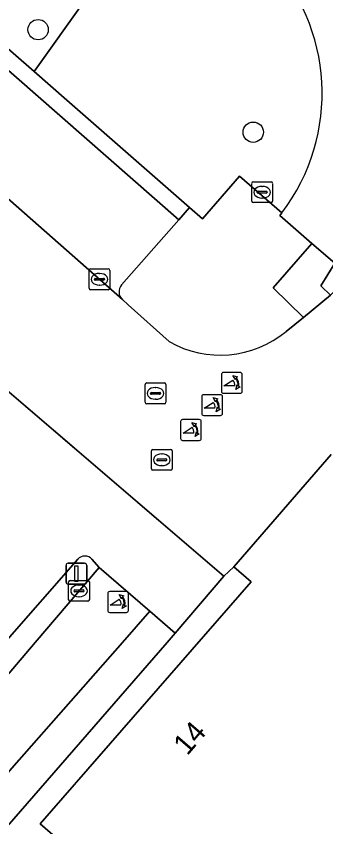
# Model space of a CAD drawing. Extents: x 158472 to 159562, y 388525 to 389606.
# Drawn here: x 158841.56 to 158856.42, y 388741.16 to 388780.05 of the extents above; entities that cross this region are included whole.
import ezdxf

# ---------------------------------------------------------------- set-up
doc = ezdxf.new("R2010")
doc.units = 0
for name, color, linetype in [('IMGEO_Boom', 7, 'Continuous'), ('IMGEO_Brandkraan', 7, 'Continuous'), ('IMGEO_Fietspad_gesloten', 7, 'Continuous'), ('IMGEO_Groenvoorziening', 7, 'Continuous'), ('IMGEO_Haag', 7, 'Continuous'), ('IMGEO_Kolk', 7, 'Continuous'), ('IMGEO_Lichtmast', 7, 'Continuous'), ('IMGEO_Pand', 7, 'Continuous'), ('IMGEO_Pand_nummerreeks', 7, 'Continuous'), ('IMGEO_Parkeervlak_open', 7, 'Continuous'), ('IMGEO_Poller', 7, 'Continuous'), ('IMGEO_Rijbaan_lokaal_open', 7, 'Continuous'), ('IMGEO_Rioolput', 7, 'Continuous'), ('IMGEO_Voetpad_open', 7, 'Continuous')]:
    doc.layers.add(name, color=color, linetype=linetype)

msp = doc.modelspace()

# ---------------------------------------------------------------- linework, layer by layer
at = {"layer": 'IMGEO_Boom'}
for centre in [(158842.61, 388779.402), (158852.939, 388774.483)]:
    msp.add_circle(centre, 0.489, dxfattribs=at)
at = {"layer": 'IMGEO_Brandkraan'}
for p, q in [((158852.867, 388771.178), (158852.867, 388772.03)), ((158852.942, 388772.104), (158853.794, 388772.104)), ((158853.868, 388772.03), (158853.868, 388771.178)), ((158853.126, 388771.598), (158853.126, 388771.61)), ((158853.169, 388771.647), (158853.567, 388771.647)), ((158853.355, 388771.884), (158853.38, 388771.884)), ((158853.61, 388771.61), (158853.61, 388771.598)), ((158853.564, 388771.561), (158853.166, 388771.561)), ((158853.378, 388771.324), (158853.353, 388771.324)), ((158853.794, 388771.104), (158852.942, 388771.104))]:
    msp.add_line(p, q, dxfattribs=at)
for points in [[(158852.867, 388771.178), (158852.867, 388772.03)], [(158852.942, 388772.104), (158853.794, 388772.104)], [(158853.868, 388772.03), (158853.868, 388771.178)], [(158853.794, 388771.104), (158852.942, 388771.104)]]:
    msp.add_lwpolyline(points, dxfattribs=at)
for centre, radius, start, end in [((158852.944, 388772.028), 0.0765, 91.552, 178.448), ((158852.944, 388772.028), 0.0765, 91.552, 178.448), ((158853.792, 388772.028), 0.0765, 1.552, 88.448), ((158853.792, 388772.028), 0.0765, 1.552, 88.448), ((158853.166, 388771.607), 0.0403, 85.8775, 175.7526), ((158853.163, 388771.597), 0.0366, 178.938, 274.7102), ((158853.567, 388771.604), 0.043, 264.8664, 352.4533), ((158853.571, 388771.609), 0.0386, 1.7309, 96.639), ((158852.944, 388771.18), 0.0765, 181.552, 268.448), ((158852.944, 388771.18), 0.0765, 181.552, 268.448), ((158853.792, 388771.18), 0.0765, 271.552, 358.448), ((158853.792, 388771.18), 0.0765, 271.552, 358.448)]:
    msp.add_arc(centre, radius, start, end, dxfattribs=at)
for centre, major_axis, ratio, start_param, end_param in [((158853.354, 388771.604), (-0.387, 0.002), 0.722429, 4.712389, 7.853982), ((158853.379, 388771.604), (-0.39, 0.002), 0.717154, 1.570796, 4.712389)]:
    msp.add_ellipse(centre, major_axis=major_axis, ratio=ratio, start_param=start_param, end_param=end_param, dxfattribs=at)
at = {"layer": 'IMGEO_Fietspad_gesloten'}
msp.add_lwpolyline([(158810.886, 388711.732), (158812.719, 388711.297), (158814.869, 388710.787), (158814.869, 388710.788), (158815.7, 388711.945), (158815.926, 388712.258), (158824.309, 388722.191), (158828.494, 388729.091), (158841.352, 388743.973), (158846.666, 388750), (158847.968, 388751.505), (158845.533, 388753.604), (158842.47, 388750), (158830.472, 388735.881), (158829.07, 388734.265), (158828.323, 388733.403), (158828.113, 388733.162), (158826.147, 388730.896), (158821.352, 388724.146), (158817.275, 388719.548), (158816.62, 388718.761), (158811.748, 388712.776), (158810.886, 388711.732), (158810.886, 388711.732)], dxfattribs=at)
at = {"layer": 'IMGEO_Groenvoorziening'}
for points in [[(158868.786, 388781.968), (158856.961, 388768.353), (158856.858, 388768.202), (158856.185, 388767.106), (158856.64, 388766.667), (158865.091, 388774.661), (158872.19, 388781.908), (158872.356, 388782.085), (158872.522, 388782.263), (158883.327, 388794.483)], [(158853.619, 388782.898), (158855.447, 388784.891), (158851.58, 388788.308), (158844.852, 388780.806), (158842.418, 388777.388), (158843.993, 388776.012), (158849.885, 388770.864), (158850.507, 388770.321), (158852.278, 388772.366), (158854.314, 388770.621)], [(158855.756, 388769.138), (158854.216, 388770.482), (158854.314, 388770.621), (158852.278, 388772.366), (158850.507, 388770.321), (158849.885, 388770.864), (158849.366, 388770.272), (158846.619, 388767.157)], [(158854.525, 388764.929), (158855.357, 388765.589), (158853.888, 388767.011), (158855.756, 388769.138)], [(158846.659, 388766.452), (158846.938, 388766.2), (158848.898, 388764.436)], [(158844.515, 388754.003), (158841.019, 388750), (158828.051, 388735.145), (158829.07, 388734.265), (158830.472, 388735.881), (158842.47, 388750)], [(158842.47, 388750), (158845.533, 388753.604), (158845.196, 388754.006)]]:
    msp.add_lwpolyline(points, dxfattribs=at)
msp.add_lwpolyline([(158834.211, 388789.462), (158831.754, 388786.709), (158832.697, 388785.881), (158842.418, 388777.388), (158844.852, 388780.806)], close=True, dxfattribs=at)
for centre, radius, start, end in [((158846.775, 388776.352), 9.47, 322.758, 43.7221), ((158846.995, 388766.825), 0.502, 138.5236, 227.971), ((158851.354, 388768.766), 4.978, 240.4377, 309.5764), ((158844.857, 388753.676), 0.473, 44.2622, 136.2426)]:
    msp.add_arc(centre, radius, start, end, dxfattribs=at)
at = {"layer": 'IMGEO_Haag'}
for points in [[(158868.786, 388781.968), (158856.961, 388768.353), (158856.858, 388768.202), (158856.185, 388767.106), (158856.64, 388766.667), (158865.091, 388774.661), (158872.19, 388781.908), (158872.356, 388782.085), (158872.522, 388782.263), (158883.327, 388794.483)], [(158844.515, 388754.003), (158841.019, 388750), (158828.051, 388735.145), (158829.07, 388734.265), (158830.472, 388735.881), (158842.47, 388750)], [(158842.47, 388750), (158845.533, 388753.604), (158845.196, 388754.006)]]:
    msp.add_lwpolyline(points, dxfattribs=at)
msp.add_arc((158844.857, 388753.676), 0.473, 44.2622, 136.2426, dxfattribs=at)
at = {"layer": 'IMGEO_Kolk'}
for p, q in [((158845.053, 388767.001), (158845.053, 388767.853)), ((158845.128, 388767.927), (158845.98, 388767.927)), ((158845.541, 388767.707), (158845.566, 388767.707)), ((158846.054, 388767.853), (158846.054, 388767.001)), ((158845.312, 388767.421), (158845.312, 388767.433)), ((158845.75, 388767.384), (158845.352, 388767.384)), ((158845.355, 388767.47), (158845.753, 388767.47)), ((158845.796, 388767.433), (158845.796, 388767.421)), ((158845.98, 388766.927), (158845.128, 388766.927)), ((158845.564, 388767.147), (158845.539, 388767.147)), ((158848.046, 388758.341), (158848.046, 388759.193)), ((158848.121, 388759.267), (158848.973, 388759.267)), ((158849.047, 388759.193), (158849.047, 388758.341)), ((158848.305, 388758.761), (158848.305, 388758.773)), ((158848.348, 388758.81), (158848.746, 388758.81)), ((158848.534, 388759.047), (158848.559, 388759.047)), ((158848.789, 388758.773), (158848.789, 388758.761)), ((158848.743, 388758.724), (158848.345, 388758.724)), ((158848.557, 388758.487), (158848.532, 388758.487)), ((158848.973, 388758.267), (158848.121, 388758.267)), ((158844.073, 388752.055), (158844.073, 388752.907)), ((158844.148, 388752.981), (158845, 388752.981)), ((158845.074, 388752.907), (158845.074, 388752.055)), ((158844.375, 388752.524), (158844.773, 388752.524)), ((158844.561, 388752.761), (158844.586, 388752.761)), ((158844.332, 388752.475), (158844.332, 388752.487)), ((158844.77, 388752.438), (158844.372, 388752.438)), ((158844.584, 388752.201), (158844.559, 388752.201)), ((158844.816, 388752.487), (158844.816, 388752.475)), ((158845, 388751.981), (158844.148, 388751.981))]:
    msp.add_line(p, q, dxfattribs=at)
for points in [[(158845.053, 388767.001), (158845.053, 388767.853)], [(158845.128, 388767.927), (158845.98, 388767.927)], [(158846.054, 388767.853), (158846.054, 388767.001)], [(158845.98, 388766.927), (158845.128, 388766.927)], [(158848.046, 388758.341), (158848.046, 388759.193)], [(158848.121, 388759.267), (158848.973, 388759.267)], [(158849.047, 388759.193), (158849.047, 388758.341)], [(158848.973, 388758.267), (158848.121, 388758.267)], [(158844.073, 388752.055), (158844.073, 388752.907)], [(158844.148, 388752.981), (158845, 388752.981)], [(158845.074, 388752.907), (158845.074, 388752.055)], [(158845, 388751.981), (158844.148, 388751.981)]]:
    msp.add_lwpolyline(points, dxfattribs=at)
for centre, radius, start, end in [((158845.13, 388767.851), 0.0765, 91.552, 178.448), ((158845.13, 388767.851), 0.0765, 91.552, 178.448), ((158845.978, 388767.851), 0.0765, 1.552, 88.448), ((158845.978, 388767.851), 0.0765, 1.552, 88.448), ((158845.352, 388767.43), 0.0403, 85.8775, 175.7526), ((158845.349, 388767.42), 0.0366, 178.938, 274.7102), ((158845.753, 388767.427), 0.043, 264.8664, 352.4533), ((158845.757, 388767.432), 0.0386, 1.7309, 96.639), ((158845.13, 388767.003), 0.0765, 181.552, 268.448), ((158845.13, 388767.003), 0.0765, 181.552, 268.448), ((158845.978, 388767.003), 0.0765, 271.552, 358.448), ((158845.978, 388767.003), 0.0765, 271.552, 358.448), ((158848.123, 388759.191), 0.0765, 91.552, 178.448), ((158848.123, 388759.191), 0.0765, 91.552, 178.448), ((158848.971, 388759.191), 0.0765, 1.552, 88.448), ((158848.971, 388759.191), 0.0765, 1.552, 88.448), ((158848.345, 388758.77), 0.0403, 85.8775, 175.7526), ((158848.342, 388758.76), 0.0366, 178.938, 274.7102), ((158848.746, 388758.767), 0.043, 264.8664, 352.4533), ((158848.75, 388758.772), 0.0386, 1.7309, 96.639), ((158848.123, 388758.343), 0.0765, 181.552, 268.448), ((158848.123, 388758.343), 0.0765, 181.552, 268.448), ((158848.971, 388758.343), 0.0765, 271.552, 358.448), ((158848.971, 388758.343), 0.0765, 271.552, 358.448), ((158844.15, 388752.905), 0.0765, 91.552, 178.448), ((158844.15, 388752.905), 0.0765, 91.552, 178.448), ((158844.998, 388752.905), 0.0765, 1.552, 88.448), ((158844.998, 388752.905), 0.0765, 1.552, 88.448), ((158844.372, 388752.484), 0.0403, 85.8775, 175.7526), ((158844.777, 388752.486), 0.0386, 1.7309, 96.639), ((158844.369, 388752.474), 0.0366, 178.938, 274.7102), ((158844.773, 388752.481), 0.043, 264.8664, 352.4533), ((158844.15, 388752.057), 0.0765, 181.552, 268.448), ((158844.15, 388752.057), 0.0765, 181.552, 268.448), ((158844.998, 388752.057), 0.0765, 271.552, 358.448), ((158844.998, 388752.057), 0.0765, 271.552, 358.448)]:
    msp.add_arc(centre, radius, start, end, dxfattribs=at)
for centre, major_axis, ratio, start_param, end_param in [((158845.54, 388767.427), (-0.387, 0.002), 0.722429, 4.712389, 7.853982), ((158845.565, 388767.427), (-0.39, 0.002), 0.717154, 1.570796, 4.712389), ((158848.533, 388758.767), (-0.387, 0.002), 0.722429, 4.712389, 7.853982), ((158848.558, 388758.767), (-0.39, 0.002), 0.717154, 1.570796, 4.712389), ((158844.56, 388752.481), (-0.387, 0.002), 0.722429, 4.712389, 7.853982), ((158844.585, 388752.481), (-0.39, 0.002), 0.717154, 1.570796, 4.712389)]:
    msp.add_ellipse(centre, major_axis=major_axis, ratio=ratio, start_param=start_param, end_param=end_param, dxfattribs=at)
at = {"layer": 'IMGEO_Lichtmast'}
for p, q in [((158843.951, 388752.903), (158843.951, 388753.703)), ((158843.951, 388753.703), (158843.951, 388752.903)), ((158844.051, 388753.803), (158844.841, 388753.803)), ((158844.841, 388753.803), (158844.051, 388753.803)), ((158844.941, 388753.703), (158844.941, 388752.903)), ((158844.941, 388752.903), (158844.941, 388753.703)), ((158844.841, 388752.803), (158844.051, 388752.803)), ((158844.051, 388752.803), (158844.841, 388752.803))]:
    msp.add_line(p, q, dxfattribs=at)
msp.add_lwpolyline([(158844.371, 388753.678), (158844.521, 388753.678), (158844.521, 388752.928), (158844.371, 388752.928), (158844.371, 388753.678)], dxfattribs=at)
for centre, start, end in [((158844.051, 388753.703), 90, 180), ((158844.051, 388753.703), 90, 180), ((158844.841, 388753.703), 0, 90), ((158844.841, 388753.703), 360, 90), ((158844.051, 388752.903), 180, 270), ((158844.051, 388752.903), 180, 270), ((158844.841, 388752.903), 270, 0), ((158844.841, 388752.903), 270, 0)]:
    msp.add_arc(centre, 0.1, start, end, dxfattribs=at)
at = {"layer": 'IMGEO_Pand'}
msp.add_lwpolyline([(158856.673, 388759.016), (158852.007, 388753.63), (158852.831, 388752.916), (158842.709, 388741.306), (158844.63, 388739.642), (158838.813, 388733.082), (158835.637, 388729.444)], dxfattribs=at)
at = {"layer": 'IMGEO_Parkeervlak_open'}
for points in [[(158846.619, 388767.157), (158849.366, 388770.272), (158832.467, 388785.083), (158831.057, 388783.391)], [(158827.828, 388783.04), (158846.659, 388766.452)]]:
    msp.add_lwpolyline(points, dxfattribs=at)
msp.add_arc((158846.995, 388766.825), 0.502, 138.5236, 227.971, dxfattribs=at)
at = {"layer": 'IMGEO_Poller'}
for p, q in [((158851.411, 388762.862), (158851.411, 388762.055)), ((158851.411, 388762.862), (158851.411, 388762.055)), ((158852.313, 388762.957), (158851.505, 388762.957)), ((158852.313, 388762.957), (158851.505, 388762.957)), ((158852.407, 388762.055), (158852.407, 388762.862)), ((158852.407, 388762.055), (158852.407, 388762.862)), ((158851.368, 388761.891), (158850.56, 388761.891)), ((158851.368, 388761.891), (158850.56, 388761.891)), ((158851.505, 388761.96), (158852.313, 388761.96)), ((158851.505, 388761.96), (158852.313, 388761.96)), ((158850.466, 388761.796), (158850.466, 388760.989)), ((158850.466, 388761.796), (158850.466, 388760.989)), ((158851.462, 388760.989), (158851.462, 388761.796)), ((158851.462, 388760.989), (158851.462, 388761.796)), ((158850.349, 388760.697), (158849.541, 388760.697)), ((158850.349, 388760.697), (158849.541, 388760.697)), ((158850.56, 388760.894), (158851.368, 388760.894)), ((158850.56, 388760.894), (158851.368, 388760.894)), ((158849.447, 388760.602), (158849.447, 388759.795)), ((158849.447, 388760.602), (158849.447, 388759.795)), ((158850.443, 388759.795), (158850.443, 388760.602)), ((158850.443, 388759.795), (158850.443, 388760.602)), ((158849.541, 388759.7), (158850.349, 388759.7)), ((158849.541, 388759.7), (158850.349, 388759.7)), ((158845.951, 388752.351), (158845.951, 388751.544)), ((158845.951, 388752.351), (158845.951, 388751.544)), ((158846.853, 388752.446), (158846.045, 388752.446)), ((158846.853, 388752.446), (158846.045, 388752.446)), ((158846.947, 388751.544), (158846.947, 388752.351)), ((158846.947, 388751.544), (158846.947, 388752.351)), ((158846.045, 388751.449), (158846.853, 388751.449)), ((158846.045, 388751.449), (158846.853, 388751.449))]:
    msp.add_line(p, q, dxfattribs=at)
for points in [[(158852.09, 388762.686), (158852.078, 388762.613), (158851.953, 388762.818)], [(158851.953, 388762.818), (158852.184, 388762.752), (158852.113, 388762.72)], [(158852.046, 388762.313), (158851.533, 388762.313), (158851.963, 388762.588)], [(158852.106, 388762.141), (158852.172, 388762.372), (158852.202, 388762.304)], [(158852.238, 388762.277), (158852.31, 388762.266), (158852.106, 388762.141)], [(158851.101, 388761.247), (158850.588, 388761.247), (158851.018, 388761.522)], [(158851.145, 388761.62), (158851.133, 388761.547), (158851.008, 388761.752)], [(158851.008, 388761.752), (158851.239, 388761.686), (158851.168, 388761.654)], [(158851.161, 388761.075), (158851.227, 388761.306), (158851.257, 388761.238)], [(158851.293, 388761.211), (158851.365, 388761.2), (158851.161, 388761.075)], [(158850.082, 388760.053), (158849.569, 388760.053), (158849.999, 388760.328)], [(158850.126, 388760.426), (158850.114, 388760.353), (158849.989, 388760.558)], [(158849.989, 388760.558), (158850.22, 388760.492), (158850.149, 388760.46)], [(158850.142, 388759.881), (158850.208, 388760.112), (158850.238, 388760.044)], [(158850.274, 388760.017), (158850.346, 388760.006), (158850.142, 388759.881)], [(158846.63, 388752.175), (158846.618, 388752.102), (158846.493, 388752.307)], [(158846.493, 388752.307), (158846.724, 388752.241), (158846.653, 388752.209)], [(158846.586, 388751.802), (158846.073, 388751.802), (158846.503, 388752.077)], [(158846.646, 388751.63), (158846.712, 388751.861), (158846.742, 388751.793)], [(158846.778, 388751.766), (158846.85, 388751.755), (158846.646, 388751.63)]]:
    msp.add_lwpolyline(points, dxfattribs=at)
for centre, radius, start, end in [((158851.505, 388762.862), 0.0946, 90, 180), ((158851.505, 388762.862), 0.0946, 90, 180), ((158851.732, 388762.373), 0.476, 351.7527, 41.1691), ((158851.732, 388762.373), 0.516, 349.3569, 42.2912), ((158852.313, 388762.862), 0.0946, 0, 90), ((158852.313, 388762.862), 0.0946, 0, 90), ((158851.718, 388762.363), 0.332, 351.3247, 42.4854), ((158850.56, 388761.796), 0.0946, 90, 180), ((158850.56, 388761.796), 0.0946, 90, 180), ((158851.368, 388761.796), 0.0946, 0, 90), ((158851.368, 388761.796), 0.0946, 0, 90), ((158851.505, 388762.055), 0.0946, 180, 270), ((158851.505, 388762.055), 0.0946, 180, 270), ((158852.313, 388762.055), 0.0946, 270, 0), ((158852.313, 388762.055), 0.0946, 270, 0), ((158850.773, 388761.297), 0.332, 351.3247, 42.4854), ((158850.787, 388761.307), 0.476, 351.7527, 41.1691), ((158850.787, 388761.307), 0.516, 349.3569, 42.2912), ((158849.541, 388760.602), 0.0946, 90, 180), ((158849.541, 388760.602), 0.0946, 90, 180), ((158850.349, 388760.602), 0.0946, 0, 90), ((158850.349, 388760.602), 0.0946, 0, 90), ((158850.56, 388760.989), 0.0946, 180, 270), ((158850.56, 388760.989), 0.0946, 180, 270), ((158851.368, 388760.989), 0.0946, 270, 0), ((158851.368, 388760.989), 0.0946, 270, 0), ((158849.754, 388760.103), 0.332, 351.3247, 42.4854), ((158849.768, 388760.113), 0.476, 351.7527, 41.1691), ((158849.768, 388760.113), 0.516, 349.3569, 42.2912), ((158849.541, 388759.795), 0.0946, 180, 270), ((158849.541, 388759.795), 0.0946, 180, 270), ((158850.349, 388759.795), 0.0946, 270, 0), ((158850.349, 388759.795), 0.0946, 270, 0), ((158846.045, 388752.351), 0.0946, 90, 180), ((158846.045, 388752.351), 0.0946, 90, 180), ((158846.272, 388751.862), 0.476, 351.7527, 41.1691), ((158846.272, 388751.862), 0.516, 349.3569, 42.2912), ((158846.853, 388752.351), 0.0946, 0, 90), ((158846.853, 388752.351), 0.0946, 0, 90), ((158846.258, 388751.852), 0.332, 351.3247, 42.4854), ((158846.045, 388751.544), 0.0946, 180, 270), ((158846.045, 388751.544), 0.0946, 180, 270), ((158846.853, 388751.544), 0.0946, 270, 0), ((158846.853, 388751.544), 0.0946, 270, 0)]:
    msp.add_arc(centre, radius, start, end, dxfattribs=at)
at = {"layer": 'IMGEO_Rijbaan_lokaal_open'}
for points in [[(158848.898, 388764.436), (158846.938, 388766.2), (158846.659, 388766.452), (158827.828, 388783.04), (158825.712, 388784.875), (158809.387, 388799.161), (158806.606, 388801.596), (158800.712, 388806.754), (158800.014, 388807.365), (158795.971, 388810.903), (158760.339, 388842.098), (158759.734, 388842.616)], [(158753.152, 388841.891), (158755.415, 388839.873), (158770.849, 388826.358), (158771.252, 388826.005), (158782.389, 388816.244), (158796.782, 388803.661), (158807.018, 388794.713), (158811.795, 388790.555), (158827.866, 388776.475), (158826.434, 388774.844), (158830.139, 388771.553), (158835.373, 388767.052), (158839.915, 388763.082), (158840.19, 388762.88), (158851.529, 388753.19), (158852.007, 388753.63), (158856.673, 388759.016)], [(158854.314, 388770.621), (158854.216, 388770.482), (158855.756, 388769.138), (158856.858, 388768.202), (158856.961, 388768.353), (158868.786, 388781.968)], [(158856.64, 388766.667), (158855.357, 388765.589), (158854.525, 388764.929)], [(158845.196, 388754.006), (158845.533, 388753.604), (158847.968, 388751.505), (158849.194, 388750.448), (158851.529, 388753.19), (158840.19, 388762.88)], [(158813.482, 388752.505), (158809.71, 388755.797), (158806.435, 388752.062), (158808.801, 388750), (158820.977, 388739.389), (158825.377, 388735.504), (158827.095, 388734.05), (158827.325, 388734.314), (158828.051, 388735.145), (158841.019, 388750), (158844.515, 388754.003)]]:
    msp.add_lwpolyline(points, dxfattribs=at)
for centre, radius, start, end in [((158846.775, 388776.352), 9.47, 322.758, 43.7221), ((158851.354, 388768.766), 4.978, 240.4377, 309.5764), ((158844.857, 388753.676), 0.473, 44.2622, 136.2426)]:
    msp.add_arc(centre, radius, start, end, dxfattribs=at)
at = {"layer": 'IMGEO_Rioolput'}
for p, q in [((158847.747, 388761.528), (158847.747, 388762.38)), ((158847.822, 388762.454), (158848.674, 388762.454)), ((158848.235, 388762.234), (158848.26, 388762.234)), ((158848.748, 388762.38), (158848.748, 388761.528)), ((158848.006, 388761.948), (158848.006, 388761.96)), ((158848.444, 388761.911), (158848.046, 388761.911)), ((158848.049, 388761.997), (158848.447, 388761.997)), ((158848.49, 388761.96), (158848.49, 388761.948)), ((158848.258, 388761.674), (158848.233, 388761.674)), ((158848.674, 388761.454), (158847.822, 388761.454))]:
    msp.add_line(p, q, dxfattribs=at)
for points in [[(158847.747, 388761.528), (158847.747, 388762.38)], [(158847.822, 388762.454), (158848.674, 388762.454)], [(158848.748, 388762.38), (158848.748, 388761.528)], [(158848.674, 388761.454), (158847.822, 388761.454)]]:
    msp.add_lwpolyline(points, dxfattribs=at)
for centre, radius, start, end in [((158847.824, 388762.378), 0.0765, 91.552, 178.448), ((158847.824, 388762.378), 0.0765, 91.552, 178.448), ((158848.672, 388762.378), 0.0765, 1.552, 88.448), ((158848.672, 388762.378), 0.0765, 1.552, 88.448), ((158848.046, 388761.957), 0.0403, 85.8775, 175.7526), ((158848.043, 388761.947), 0.0366, 178.938, 274.7102), ((158848.447, 388761.954), 0.043, 264.8664, 352.4533), ((158848.451, 388761.959), 0.0386, 1.7309, 96.639), ((158847.824, 388761.53), 0.0765, 181.552, 268.448), ((158847.824, 388761.53), 0.0765, 181.552, 268.448), ((158848.672, 388761.53), 0.0765, 271.552, 358.448), ((158848.672, 388761.53), 0.0765, 271.552, 358.448)]:
    msp.add_arc(centre, radius, start, end, dxfattribs=at)
for centre, major_axis, ratio, start_param, end_param in [((158848.234, 388761.954), (-0.387, 0.002), 0.722429, 4.712389, 7.853982), ((158848.259, 388761.954), (-0.39, 0.002), 0.717154, 1.570796, 4.712389)]:
    msp.add_ellipse(centre, major_axis=major_axis, ratio=ratio, start_param=start_param, end_param=end_param, dxfattribs=at)
at = {"layer": 'IMGEO_Voetpad_open'}
for points in [[(158831.057, 388783.391), (158832.467, 388785.083), (158849.366, 388770.272), (158849.885, 388770.864), (158843.993, 388776.012), (158842.418, 388777.388), (158832.697, 388785.881), (158831.754, 388786.709), (158831.384, 388787.033), (158831.101, 388786.744), (158830.739, 388787.059), (158830.413, 388787.343), (158814.263, 388801.394), (158814.095, 388801.54), (158813.735, 388801.853), (158808.612, 388806.31)], [(158844.63, 388739.642), (158842.709, 388741.306), (158852.831, 388752.916), (158852.007, 388753.63), (158851.529, 388753.19), (158849.194, 388750.448), (158848.804, 388750), (158836.313, 388735.661), (158833.925, 388732.919), (158830.7, 388729.178), (158829.829, 388728.167), (158829.602, 388727.804), (158827.011, 388723.543), (158833.763, 388720.491), (158835.226, 388723.726), (158836.483, 388726.508), (158836.248, 388726.622)], [(158816.717, 388710.349), (158817.461, 388711.355), (158822.477, 388717.382), (158825.4, 388720.894), (158827.011, 388723.543), (158829.602, 388727.804), (158829.829, 388728.167), (158830.7, 388729.178), (158833.925, 388732.919), (158836.313, 388735.661), (158848.804, 388750), (158849.194, 388750.448), (158847.968, 388751.505), (158846.666, 388750), (158841.352, 388743.973), (158828.494, 388729.091), (158824.309, 388722.191), (158815.926, 388712.258), (158815.7, 388711.945), (158814.869, 388710.788), (158814.869, 388710.787), (158816.717, 388710.349)]]:
    msp.add_lwpolyline(points, dxfattribs=at)
msp.add_lwpolyline([(158856.858, 388768.202), (158855.756, 388769.138), (158853.888, 388767.011), (158855.357, 388765.589), (158856.64, 388766.667), (158856.185, 388767.106)], close=True, dxfattribs=at)

# ---------------------------------------------------------------- texts
at = {"layer": 'IMGEO_Pand_nummerreeks'}
msp.add_text('14', height=1, rotation=49.2572, dxfattribs=at).set_placement((158849.77, 388744.543))

doc.saveas('drawing.dxf')
